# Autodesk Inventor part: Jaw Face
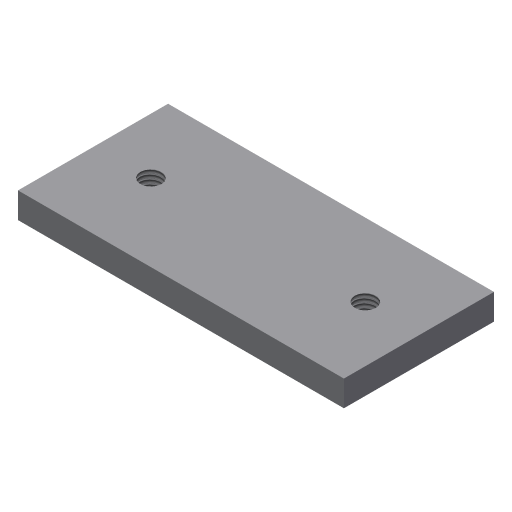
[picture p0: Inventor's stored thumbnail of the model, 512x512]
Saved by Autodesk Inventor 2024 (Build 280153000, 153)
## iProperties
Shininess: 77.0
Length Units: 11269
Angle Units: 11279
Time Units: 11290
Mass Units: 11283
Length Display Precision: 3
Angle Display Precision: 2
Compacted: True
Created: 2002-02
Part Number: Jaw Face
Document SubType Name: Modeling
Designer: ***
Density: 1 g/cm^3
Material: Generic
Mass: 15.6207 g
Surface Area: 67.651 cm^2
Volume: 15.6207 cm^3
Appearance: Default
Density: 0.0
Volumn: 0.0
Area: 0.0
PropertySet Name: Model Information
Control State: 0
Master: False
Checked Out: False
Author: ***
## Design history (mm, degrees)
sketch "Sketch1"
  geometry: L1 (-79.661, -8.43)-(-3.661, -8.43); L2 (-3.661, -8.43)-(-3.661, -43.43); L3 (-3.661, -43.43)-(-79.661, -43.43); L4 (-79.661, -43.43)-(-79.661, -8.43)
  constraints: 8 end point, 2 parallel, 1 horizontal, 1 perpendicular
  dimensions: "d0" = 76 distance of L2.end L3.end; "d3" = 35 distance of L1.end L2.end
extrude "Extrusion1" new body sketch "Sketch1" stored distance "d7" = 6; taper "d8" = 0 deg
hole "Hole1" diameter "d11" = 4.917; stored, may be unused: countersink angle "d15" = 90 deg, drill point angle "d17" = 118 deg; dims "d9" = 13, "d10" = 18, "d12" = 12, "d13" = 4, "d14" = 2, "d16" = 17.1
pattern_linear "Rectangular Pattern1" dims "d20" = -50
body "Solid1"
